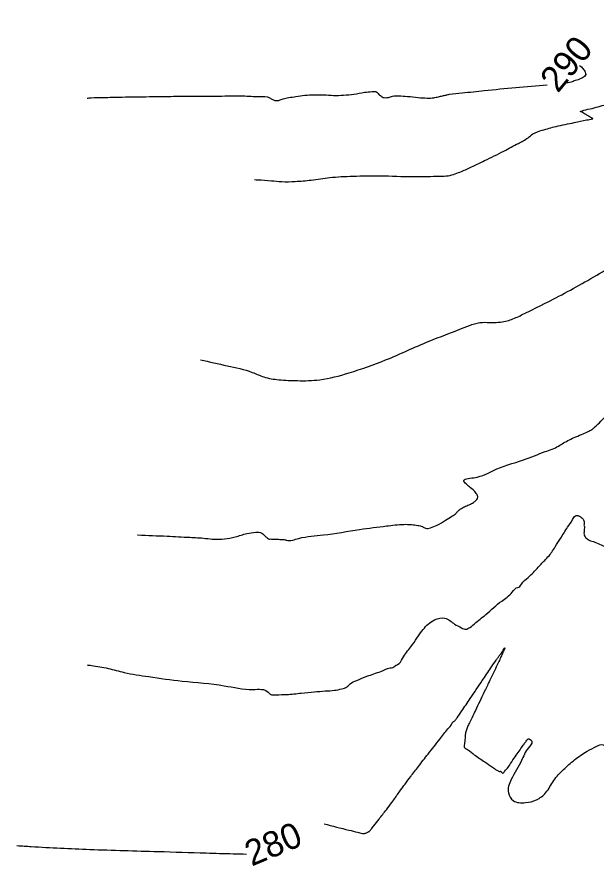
# Model space of a CAD drawing. Extents: x -475575 to -473225, y -1116053 to -1114104.
# Drawn here: x -475560.7 to -475470.4, y -1115427.3 to -1115294.8 of the extents above; entities that cross this region are included whole.
import ezdxf

# ---------------------------------------------------------------- set-up
doc = ezdxf.new("R2010")
doc.units = 0
for name, color, linetype in [('Vrstevnice_hlavni', 7, 'Continuous'), ('Vrstevnice_popis', 7, 'Continuous'), ('Vrstevnice_vedlejsi', 7, 'Continuous')]:
    doc.layers.add(name, color=color, linetype=linetype)

msp = doc.modelspace()

# ---------------------------------------------------------------- linework, layer by layer
at = {"layer": 'Vrstevnice_hlavni'}
for points in [[(-475472.93499999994, -1115302.3699999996), (-475472.41899999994, -1115302.8539999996), (-475472.2149999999, -1115303.1279999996), (-475472.06599999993, -1115303.4349999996), (-475471.9709999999, -1115303.7729999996), (-475472.1969999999, -1115304.1029999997), (-475472.74399999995, -1115304.4249999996), (-475473.6119999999, -1115304.7389999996), (-475474.27099999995, -1115304.9549999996), (-475474.7209999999, -1115305.0729999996), (-475475.2049999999, -1115305.1139999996)], [(-475519.9519824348, -1115307.838176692), (-475519.76599999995, -1115307.8019999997), (-475519.1709999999, -1115307.5889999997), (-475518.30999999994, -1115307.3889999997), (-475517.1829999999, -1115307.2019999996), (-475515.7909999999, -1115307.0279999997), (-475514.3499999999, -1115306.9429999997), (-475512.8619999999, -1115306.9469999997), (-475511.32599999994, -1115307.0399999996), (-475509.7479999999, -1115307.0059999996), (-475508.1289999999, -1115306.8479999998), (-475506.46699999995, -1115306.5629999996), (-475505.28699999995, -1115306.4539999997), (-475504.58699999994, -1115306.5209999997), (-475504.3669999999, -1115306.7629999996), (-475504.1319999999, -1115306.9809999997), (-475503.87999999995, -1115307.1759999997), (-475503.6119999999, -1115307.3469999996), (-475503.22899999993, -1115307.4039999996), (-475502.73299999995, -1115307.3459999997), (-475502.1219999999, -1115307.1739999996), (-475501.1449999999, -1115307.1219999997), (-475499.8009999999, -1115307.1909999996), (-475498.0909999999, -1115307.3819999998), (-475496.7149999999, -1115307.4559999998), (-475495.67399999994, -1115307.4129999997), (-475494.96799999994, -1115307.2549999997), (-475494.32599999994, -1115307.1109999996), (-475493.74899999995, -1115306.9809999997), (-475493.2359999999, -1115306.8659999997), (-475491.2579999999, -1115306.6349999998), (-475487.81499999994, -1115306.2899999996), (-475477.99999999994, -1115305.3679999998)], [(-475549.76099999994, -1115307.4779999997), (-475549.12499999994, -1115307.4179999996), (-475547.29299999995, -1115307.3589999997), (-475544.26599999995, -1115307.2989999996), (-475540.0419999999, -1115307.2379999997), (-475537.09699999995, -1115307.1949999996), (-475535.42999999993, -1115307.1679999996), (-475535.0409999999, -1115307.1589999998), (-475534.5909999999, -1115307.1559999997), (-475534.0789999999, -1115307.1599999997), (-475533.5069999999, -1115307.1699999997), (-475531.87999999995, -1115307.1679999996), (-475529.19999999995, -1115307.1509999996), (-475525.46699999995, -1115307.1209999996), (-475522.82499999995, -1115307.2029999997), (-475521.27599999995, -1115307.3979999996), (-475520.8179999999, -1115307.7059999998), (-475520.31499999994, -1115307.8409999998), (-475519.9519824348, -1115307.8381766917)], [(-475512.79999999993, -1115420.7169999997), (-475508.9099999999, -1115421.6909999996), (-475507.56499999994, -1115422.0239999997), (-475506.82099999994, -1115422.2019999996), (-475506.6769999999, -1115422.2259999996), (-475506.50499999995, -1115422.2069999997), (-475506.30399999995, -1115422.1439999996), (-475506.0739999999, -1115422.0379999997), (-475505.90799999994, -1115421.9659999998), (-475505.8059999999, -1115421.9289999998), (-475505.7679999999, -1115421.9269999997), (-475505.69999999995, -1115421.8709999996), (-475505.60399999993, -1115421.7619999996), (-475505.47799999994, -1115421.5999999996), (-475505.01499999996, -1115421.0029999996), (-475504.2149999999, -1115419.9719999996), (-475503.07699999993, -1115418.5059999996), (-475502.2199999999, -1115417.3759999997), (-475501.6429999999, -1115416.5839999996), (-475501.34699999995, -1115416.1279999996), (-475500.8549999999, -1115415.4349999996), (-475500.16799999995, -1115414.5029999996), (-475499.2849999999, -1115413.3339999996), (-475498.0849999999, -1115411.7739999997), (-475496.5679999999, -1115409.8229999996), (-475494.73299999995, -1115407.4829999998), (-475493.49999999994, -1115405.8999999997), (-475492.8669999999, -1115405.0759999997), (-475492.8349999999, -1115405.0089999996), (-475492.80399999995, -1115404.9539999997), (-475492.7749999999, -1115404.9089999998), (-475492.7479999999, -1115404.8739999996), (-475492.69099999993, -1115404.8269999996), (-475492.6059999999, -1115404.7669999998), (-475492.4909999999, -1115404.6929999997), (-475492.3599999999, -1115404.5709999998), (-475492.21099999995, -1115404.3989999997), (-475492.0469999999, -1115404.1769999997), (-475491.30899999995, -1115403.0959999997), (-475489.9979999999, -1115401.1539999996), (-475488.11399999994, -1115398.3529999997), (-475486.7629999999, -1115396.3569999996), (-475485.94599999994, -1115395.1649999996), (-475485.6609999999, -1115394.7779999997), (-475485.3659999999, -1115394.3599999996), (-475485.05999999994, -1115393.9119999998), (-475484.74399999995, -1115393.4319999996), (-475484.5949999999, -1115393.2469999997), (-475484.61399999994, -1115393.3549999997), (-475484.79999999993, -1115393.7559999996), (-475484.97199999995, -1115394.1329999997), (-475485.1279999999, -1115394.4849999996), (-475485.2689999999, -1115394.8119999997), (-475485.63499999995, -1115395.5949999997), (-475486.2259999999, -1115396.8339999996), (-475487.0419999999, -1115398.5279999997), (-475487.8069999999, -1115400.1209999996), (-475488.52099999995, -1115401.6129999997), (-475489.1829999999, -1115403.0019999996), (-475489.7199999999, -1115404.1219999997), (-475490.1339999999, -1115404.9729999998), (-475490.42299999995, -1115405.5539999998), (-475490.6339999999, -1115406.1739999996), (-475490.7679999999, -1115406.8319999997), (-475490.8239999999, -1115407.5299999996), (-475490.87499999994, -1115408.0559999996), (-475490.9199999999, -1115408.4119999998), (-475490.96099999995, -1115408.5969999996), (-475490.43999999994, -1115409.0999999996), (-475489.35899999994, -1115409.9209999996), (-475487.71699999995, -1115411.0609999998), (-475486.54899999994, -1115411.8619999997), (-475485.85399999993, -1115412.3249999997), (-475485.6329999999, -1115412.4499999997), (-475485.4649999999, -1115412.5219999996), (-475485.3499999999, -1115412.5419999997), (-475485.28899999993, -1115412.5089999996), (-475485.20599999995, -1115412.5429999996), (-475485.09899999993, -1115412.6439999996), (-475484.9699999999, -1115412.8109999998), (-475484.6319999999, -1115412.5489999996), (-475484.0839999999, -1115411.8579999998), (-475483.3279999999, -1115410.7369999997), (-475482.66299999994, -1115409.7639999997), (-475482.0889999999, -1115408.9369999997), (-475481.6069999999, -1115408.2579999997), (-475481.26499999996, -1115407.7889999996), (-475481.0629999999, -1115407.5289999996), (-475481.00099999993, -1115407.4789999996), (-475480.9269999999, -1115407.4589999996), (-475480.8409999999, -1115407.4679999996), (-475480.7429999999, -1115407.5079999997), (-475480.65099999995, -1115407.5609999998), (-475480.5629999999, -1115407.6279999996), (-475480.4799999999, -1115407.7079999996), (-475480.42299999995, -1115407.7719999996), (-475480.39099999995, -1115407.8189999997)], [(-475480.39099999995, -1115407.8189999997), (-475480.38499999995, -1115407.8489999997), (-475480.9209999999, -1115408.8559999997), (-475481.9979999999, -1115410.8399999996), (-475483.6169999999, -1115413.8009999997), (-475484.05299999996, -1115415.8799999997), (-475483.3059999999, -1115417.0769999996), (-475481.37599999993, -1115417.3909999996), (-475479.67499999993, -1115416.9759999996), (-475478.2039999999, -1115415.8299999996), (-475476.96199999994, -1115413.9539999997), (-475475.47299999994, -1115412.2519999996), (-475473.73899999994, -1115410.7259999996), (-475471.7579999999, -1115409.3739999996), (-475470.2739999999, -1115408.5879999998), (-475469.28799999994, -1115408.3669999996), (-475468.79899999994, -1115408.7129999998), (-475467.9979999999, -1115408.5049999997), (-475466.8839999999, -1115407.7429999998), (-475465.4579999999, -1115406.4289999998), (-475463.9919999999, -1115405.4569999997), (-475462.4859999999, -1115404.8279999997), (-475460.93899999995, -1115404.5419999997), (-475459.5909999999, -1115404.3919999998), (-475458.43999999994, -1115404.3779999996), (-475457.48799999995, -1115404.4999999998), (-475454.9149999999, -1115404.6989999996), (-475450.7209999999, -1115404.9759999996), (-475444.9059999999, -1115405.3299999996), (-475440.50599999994, -1115405.5559999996), (-475437.52199999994, -1115405.6539999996), (-475435.9529999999, -1115405.6229999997), (-475434.41199999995, -1115405.5829999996), (-475432.8999999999, -1115405.5339999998), (-475431.4169999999, -1115405.4759999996), (-475426.1929999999, -1115405.3019999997), (-475417.22899999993, -1115405.0109999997), (-475404.5239999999, -1115404.6049999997), (-475392.38099999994, -1115404.4979999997), (-475380.79899999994, -1115404.6919999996), (-475369.7789999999, -1115405.1869999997), (-475362.1989999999, -1115405.5729999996), (-475358.05999999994, -1115405.8519999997), (-475357.3599999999, -1115406.0229999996), (-475356.5999999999, -1115406.1299999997), (-475355.77699999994, -1115406.1729999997), (-475354.8929999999, -1115406.1519999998), (-475351.88699999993, -1115406.1379999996), (-475346.7589999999, -1115406.1289999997), (-475332.2569999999, -1115406.1249999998)], [(-475560.68141554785, -1115424.112180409), (-475558.4549999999, -1115424.2509999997), (-475549.33099999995, -1115424.6969999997), (-475538.6609999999, -1115425.0249999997), (-475531.2029999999, -1115425.2519999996), (-475526.9549999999, -1115425.3769999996), (-475524.87999999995, -1115425.4229999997)]]:
    msp.add_spline(points, degree=3, dxfattribs=at)
at = {"layer": 'Vrstevnice_vedlejsi'}
msp.add_line((-475541.897922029, -1115375.6166153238), (-475541.8169999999, -1115375.6299999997), dxfattribs=at)
for points in [[(-475472.2349999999, -1115374.3059999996), (-475472.1979999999, -1115374.2989999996), (-475472.1879999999, -1115374.4959999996), (-475472.20599999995, -1115374.8969999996), (-475472.2519999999, -1115375.5029999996), (-475471.9959999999, -1115376.0149999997), (-475471.4379999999, -1115376.4309999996), (-475470.57699999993, -1115376.7529999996), (-475469.56399999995, -1115377.1849999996), (-475468.3979999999, -1115377.7269999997), (-475467.0789999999, -1115378.3779999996), (-475466.13499999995, -1115378.8239999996), (-475465.56599999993, -1115379.0629999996), (-475465.3729999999, -1115379.0959999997), (-475465.13999999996, -1115378.9559999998), (-475464.86899999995, -1115378.6429999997), (-475464.55899999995, -1115378.1569999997), (-475464.2949999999, -1115377.8039999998), (-475464.07699999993, -1115377.5849999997), (-475463.9049999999, -1115377.4979999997), (-475463.7209999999, -1115377.3669999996), (-475463.5239999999, -1115377.1929999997), (-475463.31499999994, -1115376.9739999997), (-475463.10899999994, -1115376.8129999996), (-475462.9059999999, -1115376.7109999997), (-475462.70599999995, -1115376.6659999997), (-475462.54799999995, -1115376.6609999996), (-475462.4319999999, -1115376.6949999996), (-475462.3569999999, -1115376.7689999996), (-475462.3069999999, -1115376.8989999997), (-475462.28199999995, -1115377.0839999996), (-475462.2809999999, -1115377.3259999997), (-475462.4599999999, -1115377.8279999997), (-475462.82099999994, -1115378.5909999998), (-475463.3619999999, -1115379.6149999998), (-475463.22399999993, -1115380.2869999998), (-475462.4049999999, -1115380.6089999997), (-475460.90699999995, -1115380.5789999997), (-475459.05299999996, -1115380.5259999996), (-475456.8449999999, -1115380.4499999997), (-475454.28199999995, -1115380.3499999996), (-475445.2569999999, -1115380.0489999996), (-475429.7679999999, -1115379.5469999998), (-475407.8169999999, -1115378.8439999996), (-475391.76599999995, -1115378.4389999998), (-475381.61499999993, -1115378.3319999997), (-475377.36399999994, -1115378.5229999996), (-475372.95099999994, -1115378.0639999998), (-475368.37499999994, -1115376.9549999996), (-475363.63699999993, -1115375.1969999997), (-475359.09899999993, -1115374.0339999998), (-475354.7589999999, -1115373.4659999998), (-475350.61899999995, -1115373.4929999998), (-475345.00499999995, -1115372.6889999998), (-475337.9169999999, -1115371.0539999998), (-475329.3549999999, -1115368.5879999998), (-475322.00499999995, -1115365.3009999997), (-475315.8659999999, -1115361.1939999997), (-475310.93899999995, -1115356.2669999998), (-475306.26699999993, -1115351.8869999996), (-475301.8509999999, -1115348.0549999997), (-475297.69099999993, -1115344.7709999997), (-475294.1979999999, -1115340.6739999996), (-475291.3709999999, -1115335.7659999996), (-475289.21199999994, -1115330.0459999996), (-475287.57699999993, -1115325.8639999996), (-475286.46699999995, -1115323.2219999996), (-475285.88099999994, -1115322.1179999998), (-475284.97899999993, -1115320.2489999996), (-475283.76199999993, -1115317.6159999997), (-475282.22799999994, -1115314.2189999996), (-475281.12399999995, -1115311.2759999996), (-475280.4479999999, -1115308.7869999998), (-475280.20099999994, -1115306.7529999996), (-475279.9859999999, -1115303.6509999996), (-475279.8019999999, -1115299.4819999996), (-475279.65099999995, -1115294.2449999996), (-475279.53899999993, -1115290.5589999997), (-475279.4659999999, -1115288.4249999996), (-475279.4319999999, -1115287.8419999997), (-475279.3939999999, -1115287.2069999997), (-475279.35199999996, -1115286.5189999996), (-475279.3059999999, -1115285.7789999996), (-475279.42499999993, -1115284.3279999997), (-475279.7099999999, -1115282.1629999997), (-475280.1599999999, -1115279.2869999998), (-475280.78899999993, -1115274.1779999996), (-475281.59699999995, -1115266.8369999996), (-475282.5829999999, -1115257.2639999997), (-475283.3389999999, -1115250.2479999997), (-475283.86499999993, -1115245.7899999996), (-475284.1599999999, -1115243.8889999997), (-475284.6289999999, -1115241.7199999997), (-475285.2699999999, -1115239.2829999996), (-475286.0829999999, -1115236.5769999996), (-475286.62999999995, -1115234.7669999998), (-475286.9099999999, -1115233.8509999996)], [(-475523.64882547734, -1115320.1769904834), (-475523.14199999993, -1115320.2069999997), (-475521.01499999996, -1115320.3539999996), (-475519.3659999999, -1115320.5019999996), (-475517.29799999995, -1115320.4699999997), (-475514.8109999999, -1115320.2579999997), (-475511.9049999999, -1115319.8669999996), (-475508.29399999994, -1115319.6439999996), (-475503.97799999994, -1115319.5919999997), (-475498.95699999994, -1115319.7089999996), (-475495.25599999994, -1115319.6649999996), (-475492.87499999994, -1115319.4579999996), (-475491.81499999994, -1115319.0899999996), (-475490.1069999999, -1115318.3449999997), (-475487.75099999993, -1115317.2219999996), (-475484.7479999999, -1115315.7219999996), (-475482.4929999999, -1115314.5289999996), (-475480.9849999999, -1115313.6419999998), (-475480.2259999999, -1115313.0609999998), (-475478.7689999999, -1115312.4729999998), (-475476.6159999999, -1115311.8789999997), (-475473.76599999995, -1115311.2779999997), (-475471.86299999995, -1115310.8769999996), (-475470.90699999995, -1115310.6759999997), (-475470.8989999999, -1115310.6739999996), (-475470.8939999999, -1115310.6719999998), (-475470.8929999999, -1115310.6689999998), (-475470.8949999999, -1115310.6659999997), (-475470.9439999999, -1115310.6359999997), (-475471.03899999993, -1115310.5769999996), (-475471.17999999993, -1115310.4909999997), (-475471.43899999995, -1115310.3369999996), (-475471.81499999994, -1115310.1159999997), (-475472.30899999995, -1115309.8279999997), (-475472.6389999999, -1115309.6319999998), (-475472.8069999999, -1115309.5289999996), (-475472.8109999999, -1115309.5189999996), (-475472.7899999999, -1115309.5099999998), (-475472.74499999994, -1115309.5029999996), (-475472.6759999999, -1115309.4969999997), (-475472.62399999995, -1115309.4909999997), (-475472.5889999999, -1115309.4849999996), (-475472.5719999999, -1115309.4779999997), (-475471.3169999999, -1115309.1339999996), (-475468.82499999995, -1115308.4509999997), (-475465.0949999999, -1115307.4289999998), (-475462.1829999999, -1115306.6969999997), (-475460.08799999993, -1115306.2539999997), (-475458.8109999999, -1115306.0999999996), (-475457.44599999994, -1115305.8589999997), (-475455.99399999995, -1115305.5309999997), (-475454.4549999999, -1115305.1149999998), (-475453.10399999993, -1115304.8359999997), (-475451.94099999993, -1115304.6909999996), (-475450.96699999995, -1115304.6819999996), (-475450.2919999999, -1115304.6689999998), (-475449.9169999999, -1115304.6509999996), (-475449.8399999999, -1115304.6269999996), (-475449.4589999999, -1115304.4149999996), (-475448.7729999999, -1115304.0119999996), (-475447.78299999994, -1115303.4189999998), (-475446.72699999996, -1115302.8559999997), (-475445.60399999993, -1115302.3219999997)], [(-475541.8169999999, -1115375.6299999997), (-475537.2579999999, -1115375.8209999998), (-475533.7469999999, -1115375.9979999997), (-475531.2849999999, -1115376.1599999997), (-475529.8719999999, -1115376.3079999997), (-475528.32499999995, -1115376.2309999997), (-475526.6439999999, -1115375.9289999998), (-475524.8289999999, -1115375.4009999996), (-475523.4439999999, -1115375.2099999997), (-475522.48899999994, -1115375.3539999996), (-475521.9649999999, -1115375.8339999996), (-475521.5889999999, -1115376.1479999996), (-475521.3599999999, -1115376.2959999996), (-475521.2799999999, -1115376.2769999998), (-475520.97799999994, -1115376.2739999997), (-475520.4549999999, -1115376.2869999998), (-475519.7099999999, -1115376.3159999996), (-475519.1699999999, -1115376.3489999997), (-475518.8339999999, -1115376.3849999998), (-475518.7029999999, -1115376.4239999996), (-475516.7259999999, -1115376.1679999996), (-475512.9059999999, -1115375.6189999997), (-475507.23999999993, -1115374.7759999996), (-475503.0609999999, -1115374.2279999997), (-475500.3669999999, -1115373.9749999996), (-475499.15799999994, -1115374.0179999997), (-475498.18899999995, -1115374.1349999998), (-475497.4579999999, -1115374.3269999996), (-475496.9659999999, -1115374.5929999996), (-475496.1969999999, -1115374.5179999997), (-475495.15299999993, -1115374.1019999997), (-475493.83199999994, -1115373.3449999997), (-475492.84299999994, -1115372.7179999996), (-475492.1869999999, -1115372.2229999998), (-475491.86399999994, -1115371.8579999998), (-475491.3839999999, -1115371.5019999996), (-475490.7459999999, -1115371.1559999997), (-475489.94999999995, -1115370.8179999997), (-475489.36399999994, -1115370.4689999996), (-475488.9869999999, -1115370.1109999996), (-475488.8189999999, -1115369.7419999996), (-475488.95199999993, -1115369.2879999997), (-475489.38499999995, -1115368.7489999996), (-475490.11899999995, -1115368.1239999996), (-475490.6289999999, -1115367.6759999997), (-475490.9149999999, -1115367.4059999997), (-475490.9759999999, -1115367.3119999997), (-475489.4579999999, -1115366.6959999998), (-475486.3609999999, -1115365.5579999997), (-475481.68399999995, -1115363.8969999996), (-475478.30499999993, -1115362.6299999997), (-475476.22299999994, -1115361.7569999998), (-475475.43899999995, -1115361.2779999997), (-475474.53699999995, -1115360.7989999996), (-475473.51699999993, -1115360.3179999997), (-475472.37999999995, -1115359.8369999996), (-475471.50499999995, -1115359.4199999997), (-475470.89099999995, -1115359.0669999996), (-475470.5399999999, -1115358.7779999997), (-475469.6339999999, -1115357.8989999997), (-475468.17399999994, -1115356.4289999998), (-475466.1599999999, -1115354.3689999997), (-475464.2699999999, -1115352.3429999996), (-475462.50599999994, -1115350.3519999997), (-475460.8669999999, -1115348.3959999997), (-475459.4859999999, -1115346.7489999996), (-475458.36299999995, -1115345.4119999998), (-475457.4979999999, -1115344.3829999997), (-475456.2029999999, -1115342.6229999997), (-475454.47799999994, -1115340.1299999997), (-475452.3219999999, -1115336.9059999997), (-475450.78299999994, -1115334.6119999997), (-475449.8609999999, -1115333.2499999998), (-475449.5559999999, -1115332.8189999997), (-475449.19599999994, -1115332.2849999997), (-475448.78199999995, -1115331.6489999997), (-475448.3129999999, -1115330.9109999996), (-475448.0739999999, -1115330.6389999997), (-475448.0669999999, -1115330.8359999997), (-475448.28899999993, -1115331.4999999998), (-475448.47899999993, -1115332.0869999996), (-475448.63499999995, -1115332.5969999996), (-475448.7579999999, -1115333.0299999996), (-475449.1719999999, -1115334.1229999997), (-475449.87599999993, -1115335.8749999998), (-475450.86999999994, -1115338.2859999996), (-475451.5349999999, -1115339.8979999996), (-475451.86999999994, -1115340.7119999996), (-475451.87499999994, -1115340.7259999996), (-475451.87399999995, -1115340.7349999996), (-475451.8669999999, -1115340.7389999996), (-475451.85399999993, -1115340.7379999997), (-475451.84199999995, -1115340.7369999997), (-475451.83099999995, -1115340.7369999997), (-475451.82099999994, -1115340.7369999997), (-475450.9059999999, -1115340.7239999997), (-475449.0839999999, -1115340.6989999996)], [(-475532.0710680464, -1115348.2875923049), (-475527.8939999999, -1115349.2299999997), (-475523.9869999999, -1115350.2579999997), (-475522.18999999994, -1115350.9729999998), (-475519.83799999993, -1115351.4049999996), (-475516.9319999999, -1115351.5539999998), (-475513.47199999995, -1115351.4189999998), (-475508.89199999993, -1115350.3439999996), (-475503.1939999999, -1115348.3299999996), (-475496.3769999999, -1115345.3759999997), (-475491.33699999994, -1115343.4189999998), (-475488.0729999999, -1115342.4569999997), (-475486.5849999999, -1115342.4919999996), (-475485.29899999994, -1115342.4129999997), (-475484.2159999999, -1115342.2209999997), (-475483.3339999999, -1115341.9149999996), (-475481.55299999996, -1115341.0939999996), (-475478.8709999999, -1115339.7599999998), (-475475.28899999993, -1115337.9109999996), (-475471.6589999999, -1115335.9009999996), (-475467.9809999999, -1115333.7309999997)], [(-475549.75804735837, -1115395.9100298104), (-475549.0729999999, -1115395.9999999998), (-475546.4709999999, -1115396.4579999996), (-475543.9909999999, -1115397.0859999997), (-475540.1449999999, -1115397.7449999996), (-475534.9319999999, -1115398.4359999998), (-475528.35299999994, -1115399.1579999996), (-475523.8729999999, -1115399.7359999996), (-475521.4929999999, -1115400.1699999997), (-475521.2139999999, -1115400.4589999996), (-475520.26099999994, -1115400.5779999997), (-475518.63599999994, -1115400.5249999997), (-475516.3389999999, -1115400.3009999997), (-475514.32699999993, -1115400.1169999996), (-475512.6009999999, -1115399.9719999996), (-475511.1609999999, -1115399.8669999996), (-475510.03799999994, -1115399.6509999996), (-475509.23299999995, -1115399.3249999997), (-475508.7459999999, -1115398.8879999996), (-475507.7029999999, -1115398.3409999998), (-475506.10299999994, -1115397.6839999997), (-475503.9479999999, -1115396.9169999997), (-475502.4959999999, -1115396.3879999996), (-475501.74899999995, -1115396.0989999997), (-475501.7049999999, -1115396.0489999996), (-475501.61999999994, -1115395.9919999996), (-475501.4919999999, -1115395.9279999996), (-475501.32099999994, -1115395.8579999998), (-475500.57099999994, -1115394.9099999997), (-475499.2409999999, -1115393.0819999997), (-475497.3299999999, -1115390.3759999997), (-475495.5619999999, -1115388.8819999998), (-475493.93399999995, -1115388.6009999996), (-475492.4479999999, -1115389.5309999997), (-475491.3559999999, -1115390.1159999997), (-475490.65799999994, -1115390.3559999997), (-475490.35299999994, -1115390.2509999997), (-475489.3239999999, -1115389.4809999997), (-475487.56999999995, -1115388.0459999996), (-475485.09199999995, -1115385.9449999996), (-475483.4309999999, -1115384.5459999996), (-475482.58699999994, -1115383.8469999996), (-475482.5609999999, -1115383.8479999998), (-475482.01699999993, -1115383.3149999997), (-475480.95599999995, -1115382.2469999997), (-475479.3779999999, -1115380.6439999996), (-475478.23999999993, -1115379.4509999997), (-475477.5399999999, -1115378.6689999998), (-475477.2789999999, -1115378.2959999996), (-475476.7369999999, -1115377.4639999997), (-475475.91299999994, -1115376.1739999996), (-475474.8079999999, -1115374.4259999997), (-475474.02599999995, -1115373.2459999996), (-475473.56499999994, -1115372.6359999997), (-475473.4269999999, -1115372.5949999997), (-475473.2749999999, -1115372.5959999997), (-475473.10899999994, -1115372.6369999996), (-475472.92999999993, -1115372.7199999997), (-475472.74999999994, -1115372.8389999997), (-475472.5689999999, -1115372.9939999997), (-475472.38699999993, -1115373.1859999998), (-475472.2729999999, -1115373.4169999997), (-475472.22799999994, -1115373.6889999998), (-475472.25099999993, -1115374.0019999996), (-475472.2529999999, -1115374.2069999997), (-475472.2349999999, -1115374.3059999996)]]:
    msp.add_spline(points, degree=3, dxfattribs=at)

# ---------------------------------------------------------------- texts
at = {"layer": 'Vrstevnice_popis'}
for s, height, rotation, p in [(' 290 ', 4.00000000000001, 50.41104948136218, (-475477.2810421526, -1115307.9388467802)), (' 280 ', 3.9999999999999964, 22.76838966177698, (-475525.46093687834, -1115427.971969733))]:
    msp.add_text(s, height=height, rotation=rotation, dxfattribs=at).set_placement(p)

doc.saveas('drawing.dxf')
